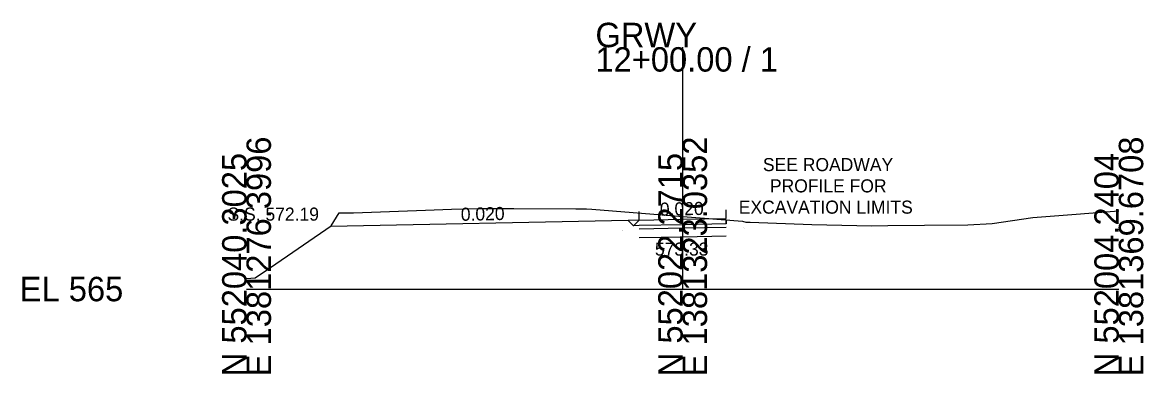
# Model space of a CAD drawing. Extents: x -26 to 103, y -10 to 3028.
# Drawn here: x -25.7 to 102.8, y 1990.3 to 2030.6 of the extents above; entities that cross this region are included whole.
import ezdxf

# ---------------------------------------------------------------- set-up
doc = ezdxf.new("R2010")
doc.units = 0
for name, color, linetype in [('Exist Cross Section Cell', 7, 'Continuous'), ('Exist XS Center Line Elevation Label', 7, 'Continuous'), ('Exist XS Ground Line', 7, 'Continuous'), ('Prop XS Dump Level', 7, 'Continuous'), ('Prop XS Earthwork Shape', 7, 'Continuous'), ('Prop XS EOT Tick Mark', 7, 'Continuous'), ('Prop XS Finish Grade', 7, 'Continuous'), ('Prop XS Finish Grade Earthwork', 7, 'Continuous'), ('Prop XS Finish Grade Pavement', 7, 'Continuous'), ('Prop XS Pvmt Edge Slope', 7, 'Continuous'), ('Prop XS SE Text', 7, 'Continuous'), ('Prop XS SS Elevation Text', 7, 'Continuous'), ('Prop XS Subgrade Earthwork', 7, 'Continuous'), ('Prop XSC Text', 7, 'Continuous')]:
    doc.layers.add(name, color=color, linetype=linetype)

msp = doc.modelspace()

# ---------------------------------------------------------------- linework, layer by layer
at = {"layer": 'Exist Cross Section Cell'}
for p, q in [((50, 2000), (50, 2027.73)), ((0, 2000), (50, 2000)), ((50, 2000), (100, 2000))]:
    msp.add_line(p, q, dxfattribs=at)
at = {"layer": 'Exist XS Ground Line'}
for p, q in [((12.27, 2008.72), (20.53, 2009.03)), ((20.53, 2009.03), (23.49, 2009.16)), ((23.49, 2009.16), (24.99, 2009.18)), ((24.99, 2009.18), (27.01, 2009.23)), ((27.01, 2009.23), (30.65, 2009.24)), ((30.65, 2009.24), (37.77, 2009.21)), ((37.77, 2009.21), (38.98, 2009.2)), ((38.98, 2009.2), (39.57, 2009.17)), ((39.57, 2009.17), (50, 2008.33)), ((94.63, 2008.55), (100, 2008.98)), ((9.69, 2007.24), (10.61, 2008.72)), ((10.61, 2008.72), (12.27, 2008.72)), ((50, 2008.33), (56.87, 2007.77)), ((56.87, 2007.77), (57.26, 2007.66)), ((85.47, 2007.51), (90.13, 2008.21)), ((90.13, 2008.21), (94.63, 2008.55)), ((2.73, 2002.48), (9.69, 2007.24)), ((57.26, 2007.66), (57.75, 2007.67)), ((57.75, 2007.67), (64.79, 2007.4)), ((64.79, 2007.4), (71.68, 2007.23)), ((71.68, 2007.23), (73.52, 2007.27)), ((73.52, 2007.27), (77.71, 2007.31)), ((77.71, 2007.31), (82.68, 2007.35)), ((82.68, 2007.35), (85.47, 2007.51)), ((0, 2001.2), (0.99, 2001.28)), ((0.99, 2001.28), (2.73, 2002.48))]:
    msp.add_line(p, q, dxfattribs=at)
at = {"layer": 'Prop XS Dump Level'}
for p, q in [((45, 2006.9), (50, 2007)), ((50, 2007), (55, 2007.1)), ((45, 2005.9), (50, 2006)), ((50, 2006), (55, 2006.1))]:
    msp.add_line(p, q, dxfattribs=at)
at = {"layer": 'Prop XS Earthwork Shape'}
msp.add_lwpolyline([(44.36, 2007.26), (43.75, 2007.87), (9.63, 2007.19), (9.69, 2007.24), (10.61, 2008.72), (12.27, 2008.72), (20.53, 2009.03), (23.49, 2009.16), (24.99, 2009.18), (27.01, 2009.23), (30.65, 2009.24), (37.77, 2009.21), (38.98, 2009.2), (39.57, 2009.17), (50, 2008.33), (55, 2007.93), (55, 2007.47), (50, 2007.38), (45, 2007.27)], close=True, dxfattribs=at)
at = {"layer": 'Prop XS EOT Tick Mark'}
for p, q in [((55, 2008.1), (55, 2009.1)), ((45, 2007.9), (45, 2008.9))]:
    msp.add_line(p, q, dxfattribs=at)
at = {"layer": 'Prop XS Finish Grade'}
msp.add_line((45, 2007.9), (43.75, 2007.87), dxfattribs=at)
at = {"layer": 'Prop XS Finish Grade Earthwork'}
msp.add_line((43.75, 2007.87), (9.63, 2007.19), dxfattribs=at)
at = {"layer": 'Prop XS Finish Grade Pavement'}
for p, q in [((45, 2007.9), (50, 2008)), ((50, 2008), (55, 2008.1))]:
    msp.add_line(p, q, dxfattribs=at)
at = {"layer": 'Prop XS Pvmt Edge Slope'}
msp.add_line((45, 2007.9), (44.36, 2007.26), dxfattribs=at)
at = {"layer": 'Prop XS Subgrade Earthwork'}
for p, q in [((44.36, 2007.26), (43.75, 2007.87)), ((55, 2007.47), (55, 2007.93)), ((45, 2007.27), (44.36, 2007.26)), ((50, 2007.38), (45, 2007.27)), ((55, 2007.47), (50, 2007.38))]:
    msp.add_line(p, q, dxfattribs=at)

# ---------------------------------------------------------------- texts
at = {"layer": 'Exist Cross Section Cell'}
for s, p in [('GRWY', (40, 2027.73)), ('12+00.00 / 1', (40, 2024.93)), ('EL 565', (-26, 1998.6))]:
    msp.add_text(s, height=2.8, dxfattribs=at).set_placement(p)
for s, p in [('E 1381276.3996', (2.8, 1990)), ('E 1381323.0352', (52.8, 1990)), ('E 1381369.6708', (102.8, 1990)), ('N 552040.3025', (0, 1990)), ('N 552022.2715', (50, 1990)), ('N 552004.2404', (100, 1990))]:
    msp.add_text(s, height=2.8, rotation=90, dxfattribs=at).set_placement(p)
at = {"layer": 'Exist XS Center Line Elevation Label'}
msp.add_text('573.33', height=1.5, dxfattribs=at).set_placement((46.82, 2003.83))
at = {"layer": 'Prop XS Dump Level'}
for p in [(43, 2006.7), (57, 2006.98)]:
    msp.add_text('Case1', height=0.04, dxfattribs=at).set_placement(p)
at = {"layer": 'Prop XS SE Text'}
for p in [(24.58, 2007.82), (47.4, 2008.4)]:
    msp.add_text('0.020', height=1.5, rotation=1.1458, dxfattribs=at).set_placement(p)
at = {"layer": 'Prop XS SS Elevation Text'}
msp.add_text('S.S. 572.19', height=1.5, dxfattribs=at).set_placement((-2.18, 2007.84))
at = {"layer": 'Prop XSC Text'}
for s, p in [('SEE ROADWAY', (59.2, 2013.52)), ('PROFILE FOR', (60, 2011.08)), ('EXCAVATION LIMITS', (56.43, 2008.64))]:
    msp.add_text(s, height=1.5, dxfattribs=at).set_placement(p)

doc.saveas('drawing.dxf')
